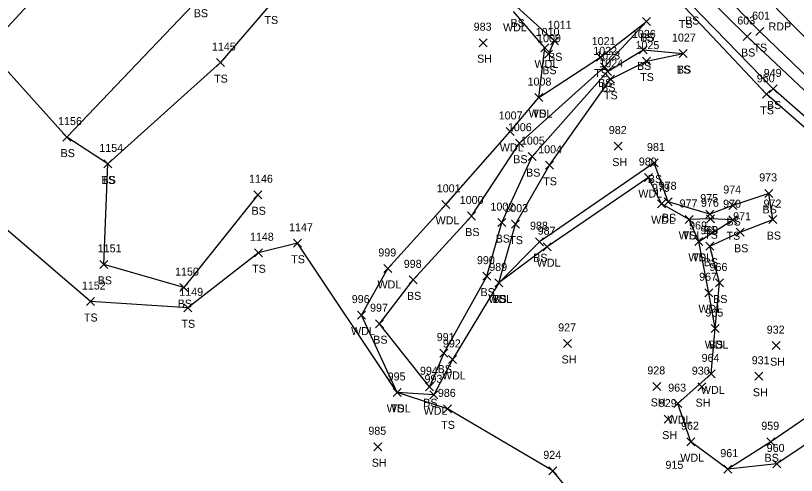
# Model space of a CAD drawing. Extents: x 1879695 to 1880991, y 836466 to 845172.
# Drawn here: x 1879796.4 to 1879991.4, y 844161 to 844275.8 of the extents above; entities that cross this region are included whole.
import ezdxf

# ---------------------------------------------------------------- set-up
doc = ezdxf.new("R2010")
doc.units = 0
for name, color, linetype in [('L_A', 7, 'Continuous'), ('L_I', 7, 'Continuous'), ('L_TIC', 7, 'Continuous'), ('LAWA', 7, 'Continuous'), ('LELB', 7, 'Continuous'), ('P_A', 7, 'Continuous'), ('PET', 7, 'Continuous')]:
    doc.layers.add(name, color=color, linetype=linetype)

msp = doc.modelspace()

# ---------------------------------------------------------------- linework, layer by layer
at = {"layer": 'L_TIC'}
for points in [[(1879952.96, 844273.38), (1879954.96, 844275.38)], [(1879954.96, 844273.38), (1879952.96, 844275.38)], [(1879952.96, 844273.38), (1879954.96, 844275.38)], [(1879954.96, 844273.38), (1879952.96, 844275.38)], [(1879981.29, 844270.84), (1879983.29, 844272.84)], [(1879983.29, 844270.84), (1879981.29, 844272.84)], [(1879929.96, 844268.54), (1879931.96, 844270.54)], [(1879931.96, 844268.54), (1879929.96, 844270.54)], [(1879978.16, 844269.62), (1879980.16, 844271.62)], [(1879980.16, 844269.62), (1879978.16, 844271.62)], [(1879912.17, 844268.08), (1879914.17, 844270.08)], [(1879914.17, 844268.08), (1879912.17, 844270.08)], [(1879927.58, 844266.77), (1879929.58, 844268.77)], [(1879929.58, 844266.77), (1879927.58, 844268.77)], [(1879928.51, 844265.2), (1879930.51, 844267.2)], [(1879930.51, 844265.2), (1879928.51, 844267.2)], [(1879952.17, 844266.27), (1879954.17, 844268.27)], [(1879954.17, 844266.27), (1879952.17, 844268.27)], [(1879962.12, 844265.36), (1879964.12, 844267.36)], [(1879964.12, 844265.36), (1879962.12, 844267.36)], [(1879962.12, 844265.36), (1879964.12, 844267.36)], [(1879964.12, 844265.36), (1879962.12, 844267.36)], [(1879846.54, 844263.1), (1879848.54, 844265.1)], [(1879848.54, 844263.1), (1879846.54, 844265.1)], [(1879941.51, 844264.47), (1879943.51, 844266.47)], [(1879943.51, 844264.47), (1879941.51, 844266.47)], [(1879953, 844263.48), (1879955, 844265.48)], [(1879955, 844263.48), (1879953, 844265.48)], [(1879942.45, 844262.04), (1879944.45, 844264.04)], [(1879944.45, 844262.04), (1879942.45, 844264.04)], [(1879943.23, 844260.88), (1879945.23, 844262.88)], [(1879945.23, 844260.88), (1879943.23, 844262.88)], [(1879943.96, 844258.93), (1879945.96, 844260.93)], [(1879945.96, 844258.93), (1879943.96, 844260.93)], [(1879982.99, 844255.18), (1879984.99, 844257.18)], [(1879984.99, 844255.18), (1879982.99, 844257.18)], [(1879984.64, 844256.52), (1879986.64, 844258.52)], [(1879986.64, 844256.52), (1879984.64, 844258.52)], [(1879926.12, 844254.36), (1879928.12, 844256.36)], [(1879928.12, 844254.36), (1879926.12, 844256.36)], [(1879926.12, 844254.36), (1879928.12, 844256.36)], [(1879928.12, 844254.36), (1879926.12, 844256.36)], [(1879918.92, 844245.9), (1879920.92, 844247.9)], [(1879920.92, 844245.9), (1879918.92, 844247.9)], [(1879808.17, 844244.49), (1879810.17, 844246.49)], [(1879810.17, 844244.49), (1879808.17, 844246.49)], [(1879808.17, 844244.49), (1879810.17, 844246.49)], [(1879810.17, 844244.49), (1879808.17, 844246.49)], [(1879921.26, 844242.96), (1879923.26, 844244.96)], [(1879923.26, 844242.96), (1879921.26, 844244.96)], [(1879945.93, 844242.24), (1879947.93, 844244.24)], [(1879947.93, 844242.24), (1879945.93, 844244.24)], [(1879924.46, 844239.61), (1879926.46, 844241.61)], [(1879926.46, 844239.61), (1879924.46, 844241.61)], [(1879818.41, 844237.78), (1879820.41, 844239.78)], [(1879820.41, 844237.78), (1879818.41, 844239.78)], [(1879818.41, 844237.78), (1879820.41, 844239.78)], [(1879820.41, 844237.78), (1879818.41, 844239.78)], [(1879928.77, 844237.44), (1879930.77, 844239.44)], [(1879930.77, 844237.44), (1879928.77, 844239.44)], [(1879954.89, 844238.02), (1879956.89, 844240.02)], [(1879956.89, 844238.02), (1879954.89, 844240.02)], [(1879953.52, 844234.38), (1879955.52, 844236.38)], [(1879955.52, 844234.38), (1879953.52, 844236.38)], [(1879855.87, 844230.08), (1879857.87, 844232.08)], [(1879857.87, 844230.08), (1879855.87, 844232.08)], [(1879983.51, 844230.42), (1879985.51, 844232.42)], [(1879985.51, 844230.42), (1879983.51, 844232.42)], [(1879902.88, 844227.68), (1879904.88, 844229.68)], [(1879904.88, 844227.68), (1879902.88, 844229.68)], [(1879956.73, 844227.82), (1879958.73, 844229.82)], [(1879958.73, 844227.82), (1879956.73, 844229.82)], [(1879958.38, 844228.33), (1879960.38, 844230.33)], [(1879960.38, 844228.33), (1879958.38, 844230.33)], [(1879974.52, 844227.39), (1879976.52, 844229.39)], [(1879976.52, 844227.39), (1879974.52, 844229.39)], [(1879909.27, 844224.77), (1879911.27, 844226.77)], [(1879911.27, 844224.77), (1879909.27, 844226.77)], [(1879963.61, 844223.91), (1879965.61, 844225.91)], [(1879965.61, 844223.91), (1879963.61, 844225.91)], [(1879963.61, 844223.91), (1879965.61, 844225.91)], [(1879965.61, 844223.91), (1879963.61, 844225.91)], [(1879968.77, 844225.26), (1879970.77, 844227.26)], [(1879970.77, 844225.26), (1879968.77, 844227.26)], [(1879969, 844224.08), (1879971, 844226.08)], [(1879971, 844224.08), (1879969, 844226.08)], [(1879974.57, 844223.83), (1879976.57, 844225.83)], [(1879976.57, 844223.83), (1879974.57, 844225.83)], [(1879984.58, 844223.88), (1879986.58, 844225.88)], [(1879986.58, 844223.88), (1879984.58, 844225.88)], [(1879916.85, 844223.12), (1879918.85, 844225.12)], [(1879918.85, 844223.12), (1879916.85, 844225.12)], [(1879920.29, 844222.74), (1879922.29, 844224.74)], [(1879922.29, 844222.74), (1879920.29, 844224.74)], [(1879976.42, 844220.7), (1879978.42, 844222.7)], [(1879978.42, 844220.7), (1879976.42, 844222.7)], [(1879865.82, 844217.96), (1879867.82, 844219.96)], [(1879867.82, 844217.96), (1879865.82, 844219.96)], [(1879926.24, 844218.34), (1879928.24, 844220.34)], [(1879928.24, 844218.34), (1879926.24, 844220.34)], [(1879966.04, 844218.41), (1879968.04, 844220.41)], [(1879968.04, 844218.41), (1879966.04, 844220.41)], [(1879966.04, 844218.41), (1879968.04, 844220.41)], [(1879968.04, 844218.41), (1879966.04, 844220.41)], [(1879928.15, 844217.1), (1879930.15, 844219.1)], [(1879930.15, 844217.1), (1879928.15, 844219.1)], [(1879968.84, 844217.22), (1879970.84, 844219.22)], [(1879970.84, 844217.22), (1879968.84, 844219.22)], [(1879856.04, 844215.58), (1879858.04, 844217.58)], [(1879858.04, 844215.58), (1879856.04, 844217.58)], [(1879817.44, 844212.69), (1879819.44, 844214.69)], [(1879819.44, 844212.69), (1879817.44, 844214.69)], [(1879888.36, 844211.66), (1879890.36, 844213.66)], [(1879890.36, 844211.66), (1879888.36, 844213.66)], [(1879894.7, 844208.82), (1879896.7, 844210.82)], [(1879896.7, 844208.82), (1879894.7, 844210.82)], [(1879913.07, 844209.74), (1879915.07, 844211.74)], [(1879915.07, 844209.74), (1879913.07, 844211.74)], [(1879913.07, 844209.74), (1879915.07, 844211.74)], [(1879915.07, 844209.74), (1879913.07, 844211.74)], [(1879916.07, 844208.04), (1879918.07, 844210.04)], [(1879918.07, 844208.04), (1879916.07, 844210.04)], [(1879916.07, 844208.04), (1879918.07, 844210.04)], [(1879918.07, 844208.04), (1879916.07, 844210.04)], [(1879916.07, 844208.04), (1879918.07, 844210.04)], [(1879918.07, 844208.04), (1879916.07, 844210.04)], [(1879971.19, 844208.03), (1879973.19, 844210.03)], [(1879973.19, 844208.03), (1879971.19, 844210.03)], [(1879837.42, 844206.88), (1879839.42, 844208.88)], [(1879839.42, 844206.88), (1879837.42, 844208.88)], [(1879968.55, 844205.59), (1879970.55, 844207.59)], [(1879970.55, 844205.59), (1879968.55, 844207.59)], [(1879814.05, 844203.4), (1879816.05, 844205.4)], [(1879816.05, 844203.4), (1879814.05, 844205.4)], [(1879838.4, 844201.83), (1879840.4, 844203.83)], [(1879840.4, 844201.83), (1879838.4, 844203.83)], [(1879838.4, 844201.83), (1879840.4, 844203.83)], [(1879840.4, 844201.83), (1879838.4, 844203.83)], [(1879881.77, 844200.01), (1879883.77, 844202.01)], [(1879883.77, 844200.01), (1879881.77, 844202.01)], [(1879886.28, 844197.86), (1879888.28, 844199.86)], [(1879888.28, 844197.86), (1879886.28, 844199.86)], [(1879970.11, 844196.64), (1879972.11, 844198.64)], [(1879972.11, 844196.64), (1879970.11, 844198.64)], [(1879970.11, 844196.64), (1879972.11, 844198.64)], [(1879972.11, 844196.64), (1879970.11, 844198.64)], [(1879933.28, 844192.93), (1879935.28, 844194.93)], [(1879935.28, 844192.93), (1879933.28, 844194.93)], [(1879985.39, 844192.37), (1879987.39, 844194.37)], [(1879987.39, 844192.37), (1879985.39, 844194.37)], [(1879902.37, 844190.52), (1879904.37, 844192.52)], [(1879904.37, 844190.52), (1879902.37, 844192.52)], [(1879904.49, 844188.93), (1879906.49, 844190.93)], [(1879906.49, 844188.93), (1879904.49, 844190.93)], [(1879969.15, 844185.32), (1879971.15, 844187.32)], [(1879971.15, 844185.32), (1879969.15, 844187.32)], [(1879981.06, 844184.73), (1879983.06, 844186.73)], [(1879983.06, 844184.73), (1879981.06, 844186.73)], [(1879890.68, 844180.68), (1879892.68, 844182.68)], [(1879892.68, 844180.68), (1879890.68, 844182.68)], [(1879890.68, 844180.68), (1879892.68, 844182.68)], [(1879892.68, 844180.68), (1879890.68, 844182.68)], [(1879898.76, 844182.1), (1879900.76, 844184.1)], [(1879900.76, 844182.1), (1879898.76, 844184.1)], [(1879955.55, 844182.19), (1879957.55, 844184.19)], [(1879957.55, 844182.19), (1879955.55, 844184.19)], [(1879966.77, 844182.12), (1879968.77, 844184.12)], [(1879968.77, 844182.12), (1879966.77, 844184.12)], [(1879899.88, 844180.1), (1879901.88, 844182.1)], [(1879901.88, 844180.1), (1879899.88, 844182.1)], [(1879960.82, 844177.88), (1879962.82, 844179.88)], [(1879962.82, 844177.88), (1879960.82, 844179.88)], [(1879903.28, 844176.57), (1879905.28, 844178.57)], [(1879905.28, 844176.57), (1879903.28, 844178.57)], [(1879958.43, 844174.02), (1879960.43, 844176.02)], [(1879960.43, 844174.02), (1879958.43, 844176.02)], [(1879885.86, 844167.11), (1879887.86, 844169.11)], [(1879887.86, 844167.11), (1879885.86, 844169.11)], [(1879964.02, 844168.37), (1879966.02, 844170.37)], [(1879966.02, 844168.37), (1879964.02, 844170.37)], [(1879984.03, 844168.35), (1879986.03, 844170.35)], [(1879986.03, 844168.35), (1879984.03, 844170.35)], [(1879973.27, 844161.51), (1879975.27, 844163.51)], [(1879975.27, 844161.51), (1879973.27, 844163.51)], [(1879973.27, 844161.51), (1879975.27, 844163.51)], [(1879975.27, 844161.51), (1879973.27, 844163.51)], [(1879985.51, 844162.82), (1879987.51, 844164.82)], [(1879987.51, 844162.82), (1879985.51, 844164.82)], [(1879929.57, 844161.09), (1879931.57, 844163.09)], [(1879931.57, 844161.09), (1879929.57, 844163.09)]]:
    msp.add_lwpolyline(points, dxfattribs=at)
at = {"layer": 'LAWA'}
msp.add_lwpolyline([(1880005.38, 844176.44), (1879986.51, 844163.82), (1879974.27, 844162.51), (1879965.02, 844169.37), (1879961.82, 844178.88), (1879970.15, 844186.32), (1879971.11, 844197.64), (1879969.55, 844206.59), (1879967.04, 844219.41), (1879964.61, 844224.91), (1879957.73, 844228.82), (1879954.52, 844235.38), (1879929.15, 844218.1), (1879917.07, 844209.04), (1879905.49, 844189.93), (1879900.88, 844181.1), (1879891.68, 844181.68), (1879882.77, 844201.01), (1879889.36, 844212.66), (1879903.88, 844228.68), (1879919.92, 844246.9), (1879927.12, 844255.36), (1879928.58, 844267.77), (1879920.72, 844276.91)], dxfattribs=at)
at = {"layer": 'LELB'}
for points in [[(1880237.65, 844030.17), (1880225.55, 844045.25), (1880203.19, 844067.94), (1880175.04, 844095.38), (1880141.55, 844124.24), (1880111.59, 844152.12), (1880079.67, 844179.09), (1880044.89, 844208.16), (1880013.5, 844237.54), (1880003.34, 844247.82), (1879979.16, 844270.62), (1879948.51, 844300.87), (1879928.97, 844335.67), (1879901.59, 844373.87), (1879881.39, 844405.75), (1879863.37, 844445.07), (1879846.41, 844479.41), (1879833.35, 844517.23), (1879821, 844560.9), (1879811.24, 844600.26), (1879800.64, 844646.71), (1879794.2, 844680.16), (1879792.03, 844683.6), (1879789.08, 844683.63)], [(1880243.53, 844023.94), (1880226.64, 844046.28), (1880204.68, 844069.12), (1880177.19, 844097.39), (1880144.15, 844127.37), (1880114.34, 844154.46), (1880082.65, 844181.38), (1880047.53, 844211.78), (1880015.32, 844240.12), (1879982.29, 844271.84), (1879951.96, 844303.04), (1879930.28, 844336.91), (1879904.08, 844374.32), (1879883.92, 844406.9), (1879866.98, 844446.02), (1879852.23, 844482.49), (1879838.68, 844519.35), (1879826.86, 844562.48), (1879815.22, 844600.52)], [(1880002.51, 844242.73), (1879985.64, 844257.52), (1879965.17, 844278.62), (1879940.72, 844305.37), (1879925.82, 844326.46), (1879896.67, 844370.14), (1879885.64, 844389.62), (1879876.9, 844403.13), (1879868.08, 844418.79), (1879858.9, 844415.1), (1879849.52, 844405.96), (1879835.24, 844394.65), (1879817.98, 844385.29), (1879800.66, 844373.71), (1879774.59, 844370.4), (1879756.19, 844355.96), (1879741.66, 844350.26)], [(1880061.24, 844186.41), (1880044.41, 844199.51), (1880029.44, 844214.36), (1880014.82, 844229.08), (1880001.48, 844240.9), (1879983.99, 844256.18), (1879963.67, 844277.76), (1879939.18, 844304.48), (1879924.63, 844325.43), (1879894.06, 844369.68)], [(1879910.55, 844332.26), (1879888.37, 844313.9), (1879874.46, 844304.26), (1879861.88, 844291.31), (1879842.44, 844280.44), (1879809.17, 844245.49)], [(1879909.9, 844328.44), (1879888.55, 844310.96), (1879880.16, 844302.26), (1879875.49, 844290.2), (1879860.13, 844278.75), (1879847.54, 844264.1), (1879819.41, 844238.78)], [(1879929.51, 844266.2), (1879930.96, 844269.54), (1879921.57, 844278.01), (1879918.04, 844290.27), (1879920.19, 844296.47), (1879935.63, 844299.68)], [(1879856.87, 844231.08), (1879838.42, 844207.88), (1879818.44, 844213.69), (1879819.41, 844238.78), (1879809.17, 844245.49), (1879789.24, 844267.52), (1879810.46, 844290.57)], [(1879914.07, 844210.74), (1879903.37, 844191.52), (1879899.76, 844183.1), (1879887.28, 844198.86), (1879895.7, 844209.82), (1879910.27, 844225.77), (1879922.26, 844243.96), (1879943.45, 844263.04), (1879953.96, 844274.38)], [(1879927.12, 844255.36), (1879942.51, 844265.47), (1879953.96, 844274.38)], [(1879914.07, 844210.74), (1879917.85, 844224.12), (1879925.46, 844240.61), (1879944.23, 844261.88), (1879953.17, 844267.27), (1879963.12, 844266.36)], [(1879917.07, 844209.04), (1879921.29, 844223.74), (1879929.77, 844238.44), (1879944.96, 844259.93), (1879954, 844264.48), (1879963.12, 844266.36)], [(1879839.4, 844202.83), (1879815.05, 844204.4), (1879773.28, 844240.26)], [(1879971.11, 844197.64), (1879972.19, 844209.03), (1879969.84, 844218.22), (1879977.42, 844221.7), (1879985.58, 844224.88), (1879984.51, 844231.42), (1879975.52, 844228.39), (1879969.77, 844226.26), (1879959.38, 844229.33), (1879955.89, 844239.02), (1879927.24, 844219.34), (1879917.07, 844209.04)], [(1879967.04, 844219.41), (1879975.57, 844224.83), (1879970, 844225.08), (1879964.61, 844224.91)], [(1880000.41, 844108.08), (1879970.63, 844126.53), (1879949.63, 844139.05), (1879930.57, 844162.09), (1879904.28, 844177.57), (1879891.68, 844181.68), (1879866.82, 844218.96), (1879857.04, 844216.58), (1879839.4, 844202.83)], [(1880020.4, 844184.31), (1879998.26, 844178.45), (1879985.03, 844169.35), (1879974.27, 844162.51)]]:
    msp.add_lwpolyline(points, dxfattribs=at)
at = {"layer": 'PET'}
msp.add_lwpolyline([(1880246.17, 844024.86), (1880229.35, 844048.54), (1880207.67, 844072.23), (1880179.65, 844099.99), (1880146.48, 844130.19), (1880116.3, 844156.76), (1880085.61, 844184.86), (1880050.42, 844215.32), (1880017.65, 844245.83), (1879986.99, 844277.13), (1879959.04, 844308.59), (1879934.2, 844340.79), (1879910.26, 844378.73), (1879891.14, 844411.43), (1879872.36, 844448.44), (1879856.33, 844484.43), (1879842.37, 844521.56), (1879829.6, 844563.28), (1879820.43, 844602.23)], dxfattribs=at)

# ---------------------------------------------------------------- texts
at = {"layer": 'L_A'}
for s, p in [('BS', (1879840.88, 844275.44)), ('TS', (1879858.54, 844273.75)), ('BS', (1879920.01, 844273.01)), ('TS', (1879962.08, 844272.76)), ('BS', (1879963.62, 844273.62)), ('WDL', (1879918.14, 844271.91)), ('TS', (1879952.37, 844269.38)), ('BS', (1879952.4, 844269.38)), ('TS', (1879980.7, 844266.84)), ('BS', (1879929.4, 844264.54)), ('BS', (1879977.6, 844265.62)), ('SH', (1879911.66, 844264.08)), ('WDL', (1879926, 844262.77)), ('BS', (1879927.95, 844261.2)), ('BS', (1879951.61, 844262.27)), ('TS', (1879961.53, 844261.36)), ('BS', (1879961.56, 844261.36)), ('TS', (1879845.95, 844259.1)), ('TS', (1879940.92, 844260.47)), ('TS', (1879952.41, 844259.48)), ('BS', (1879941.89, 844258.04)), ('BS', (1879942.67, 844256.88)), ('TS', (1879943.37, 844254.93)), ('TS', (1879982.4, 844251.18)), ('BS', (1879984.08, 844252.52)), ('WDL', (1879924.54, 844250.36)), ('TS', (1879925.53, 844250.36)), ('WDL', (1879917.34, 844241.9)), ('BS', (1879807.61, 844240.49)), ('BS', (1879807.61, 844240.49)), ('BS', (1879920.7, 844238.96)), ('SH', (1879945.42, 844238.24)), ('BS', (1879923.9, 844235.61)), ('TS', (1879817.81, 844233.78)), ('BS', (1879817.85, 844233.78)), ('TS', (1879928.18, 844233.44)), ('BS', (1879954.33, 844234.02)), ('WDL', (1879951.94, 844230.38)), ('BS', (1879855.31, 844226.08)), ('BS', (1879982.96, 844226.42)), ('WDL', (1879901.29, 844223.68)), ('WDL', (1879955.15, 844223.82)), ('BS', (1879957.82, 844224.33)), ('BS', (1879973.97, 844223.39)), ('BS', (1879908.71, 844220.77)), ('WDL', (1879962.03, 844219.91)), ('TS', (1879963.02, 844219.91)), ('BS', (1879968.21, 844221.26)), ('TS', (1879968.41, 844220.08)), ('TS', (1879973.97, 844219.83)), ('BS', (1879984.02, 844219.88)), ('BS', (1879916.29, 844219.12)), ('TS', (1879919.7, 844218.74)), ('BS', (1879975.86, 844216.7)), ('TS', (1879865.23, 844213.96)), ('BS', (1879925.68, 844214.34)), ('WDL', (1879964.45, 844214.41)), ('TS', (1879965.45, 844214.41)), ('WDL', (1879926.57, 844213.1)), ('BS', (1879968.29, 844213.22)), ('TS', (1879855.45, 844211.58)), ('BS', (1879816.88, 844208.69)), ('WDL', (1879886.78, 844207.66)), ('BS', (1879894.14, 844204.82)), ('BS', (1879912.51, 844205.74)), ('BS', (1879912.51, 844205.74)), ('TS', (1879915.48, 844204.04)), ('BS', (1879915.51, 844204.04)), ('BS', (1879970.63, 844204.03)), ('BS', (1879836.86, 844202.88)), ('WDL', (1879914.49, 844204.04)), ('WDL', (1879966.97, 844201.59)), ('TS', (1879813.45, 844199.4)), ('TS', (1879837.8, 844197.83)), ('TS', (1879837.8, 844197.83)), ('WDL', (1879880.18, 844196.01)), ('BS', (1879885.72, 844193.86)), ('WDL', (1879968.53, 844192.64)), ('BS', (1879969.55, 844192.64)), ('SH', (1879932.77, 844188.93)), ('BS', (1879901.81, 844186.52)), ('SH', (1879984.87, 844188.37)), ('WDL', (1879902.9, 844184.93)), ('WDL', (1879967.57, 844181.32)), ('SH', (1879980.55, 844180.73)), ('BS', (1879898.2, 844178.1)), ('SH', (1879955.04, 844178.19)), ('SH', (1879966.25, 844178.12)), ('WDL', (1879889.1, 844176.68)), ('TS', (1879890.09, 844176.68)), ('WDL', (1879898.3, 844176.1)), ('WDL', (1879959.24, 844173.88)), ('TS', (1879902.69, 844172.57)), ('SH', (1879957.91, 844170.02)), ('SH', (1879885.35, 844163.11)), ('WDL', (1879962.43, 844164.37)), ('BS', (1879983.47, 844164.35))]:
    msp.add_text(s, height=2, dxfattribs=at).set_placement(p)
at = {"layer": 'L_I'}
for s, p in [('601', (1879980.37, 844274.84)), ('1011', (1879929.32, 844272.54)), ('603', (1879976.67, 844273.62)), ('983', (1879910.81, 844272.08)), ('1010', (1879926.29, 844270.77)), ('1009', (1879926.65, 844269.2)), ('1021', (1879940.3, 844268.47)), ('1026', (1879950.34, 844270.27)), ('1027', (1879960.35, 844269.36)), ('1027', (1879960.35, 844269.36)), ('1145', (1879845.41, 844267.1)), ('1025', (1879951.23, 844267.48)), ('1022', (1879940.68, 844266.04)), ('1023', (1879941.45, 844264.88)), ('1024', (1879942.19, 844262.93)), ('950', (1879981.54, 844259.18)), ('949', (1879983.27, 844260.52)), ('1008', (1879924.27, 844258.36)), ('1008', (1879924.27, 844258.36)), ('1007', (1879917.07, 844249.9)), ('1156', (1879806.98, 844248.49)), ('1156', (1879806.98, 844248.49)), ('1006', (1879919.35, 844246.96)), ('982', (1879944.57, 844246.24)), ('1005', (1879922.61, 844243.61)), ('1154', (1879817.28, 844241.78)), ('1154', (1879817.28, 844241.78)), ('1004', (1879926.92, 844241.44)), ('981', (1879954.1, 844242.02)), ('980', (1879952.07, 844238.38)), ('1146', (1879854.69, 844234.08)), ('973', (1879982.15, 844234.42)), ('1001', (1879901.59, 844231.68)), ('979', (1879955.36, 844231.82)), ('978', (1879957.02, 844232.33)), ('974', (1879973.16, 844231.39)), ('1000', (1879907.33, 844228.77)), ('977', (1879962.25, 844227.91)), ('977', (1879962.25, 844227.91)), ('975', (1879967.41, 844229.26)), ('976', (1879967.59, 844228.08)), ('970', (1879973.12, 844227.83)), ('972', (1879983.22, 844227.88)), ('1002', (1879915, 844227.12)), ('1003', (1879918.44, 844226.74)), ('971', (1879975.63, 844224.7)), ('1147', (1879864.69, 844221.96)), ('988', (1879924.88, 844222.34)), ('969', (1879964.62, 844222.41)), ('969', (1879964.62, 844222.41)), ('987', (1879926.79, 844221.1)), ('968', (1879967.43, 844221.22)), ('1148', (1879854.91, 844219.58)), ('1151', (1879816.88, 844216.69)), ('999', (1879886.99, 844215.66)), ('998', (1879893.34, 844212.82)), ('990', (1879911.62, 844213.74)), ('990', (1879911.62, 844213.74)), ('989', (1879914.7, 844212.04)), ('989', (1879914.7, 844212.04)), ('989', (1879914.7, 844212.04)), ('966', (1879969.73, 844212.03)), ('1150', (1879836.21, 844210.88)), ('967', (1879967.14, 844209.59)), ('1152', (1879812.92, 844207.4)), ('1149', (1879837.26, 844205.83)), ('1149', (1879837.26, 844205.83)), ('996', (1879880.35, 844204.01)), ('997', (1879884.92, 844201.86)), ('965', (1879968.7, 844200.64)), ('965', (1879968.7, 844200.64)), ('927', (1879931.92, 844196.93)), ('932', (1879984.02, 844196.37)), ('991', (1879901.58, 844194.52)), ('992', (1879903.12, 844192.93)), ('964', (1879967.75, 844189.32)), ('931', (1879980.27, 844188.73)), ('995', (1879889.32, 844184.68)), ('995', (1879889.32, 844184.68)), ('994', (1879897.39, 844186.1)), ('928', (1879954.19, 844186.19)), ('930', (1879965.32, 844186.12)), ('993', (1879898.52, 844184.1)), ('963', (1879959.41, 844181.88)), ('986', (1879901.86, 844180.57)), ('929', (1879957.06, 844178.02)), ('985', (1879884.5, 844171.11)), ('962', (1879962.61, 844172.37)), ('959', (1879982.66, 844172.35)), ('924', (1879928.2, 844165.09)), ('961', (1879972.42, 844165.51)), ('961', (1879972.42, 844165.51)), ('960', (1879984.01, 844166.82)), ('915', (1879958.72, 844162.6))]:
    msp.add_text(s, height=2, dxfattribs=at).set_placement(p)
at = {"layer": 'P_A'}
msp.add_text('RDP', height=2, dxfattribs=at).set_placement((1879984.48, 844272.13))

doc.saveas('drawing.dxf')
